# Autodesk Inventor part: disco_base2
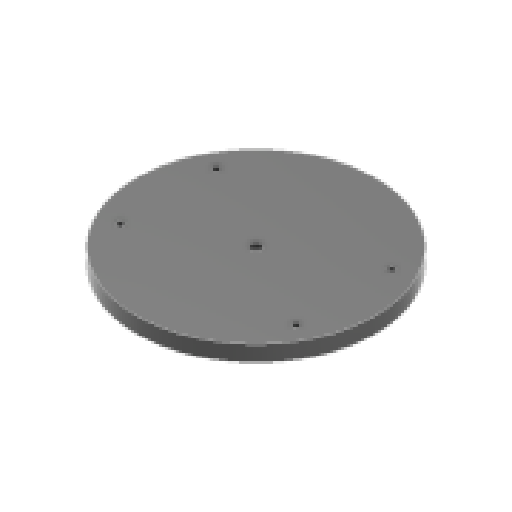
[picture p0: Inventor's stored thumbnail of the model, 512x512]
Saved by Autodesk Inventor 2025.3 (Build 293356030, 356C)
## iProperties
Created: 2026-03
Part Number: disco_base2
Material: Plastica ABS
Document SubType Name: Modeling
Designer: R5800u
Density: 1.06 g/cm^3
Appearance: Liscia - Nero
Author: R5800u
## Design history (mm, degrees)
sketch "Schizzo1"
  geometry: C1 r 75 at (0, 0); 1 further point
  constraints: 1 centre point, 1 coincident
  dimensions: "d0" = 150 diameter of C1
extrude "Estrusione1" new body sketch "Schizzo1" distance "d1" = 10; taper "d2" = 0 deg
sketch "Schizzo2"
  geometry: C1 r 75 at (0, 0) reference; 3 further points
  constraints: 1 coincident
hole "Foro1" sketch "Schizzo2" at (0, 0) diameter "d3" = 3.4; stored, may be unused: countersink angle "d7" = 82 deg, drill point angle "d9" = 118 deg; dims "d4" = 6, "d5" = 6.5, "d6" = 3.4, "d8" = 8
sketch "Schizzo4"
  geometry: C1 r 1.6 at (-55, 30) reference; C2 r 1.6 at (-55, -30) reference; C3 r 1.6 at (55, -30) reference; C4 r 1.6 at (55, 30) reference; 1 further point
hole "Foro2" sketch "Schizzo4" at (-55, 30), (-55, -30), (55, 30), (55, -30) diameter "d14" = 4.3; stored, may be unused: countersink angle "d18" = 90 deg, drill point angle "d20" = 118 deg; dims "d15" = 6, "d16" = 7.5, "d17" = 3, "d19" = 8
node "Solido1"
node "Riferimento5"
node "Riferimento6"
node "Riferimento7"
node "Riferimento8"
